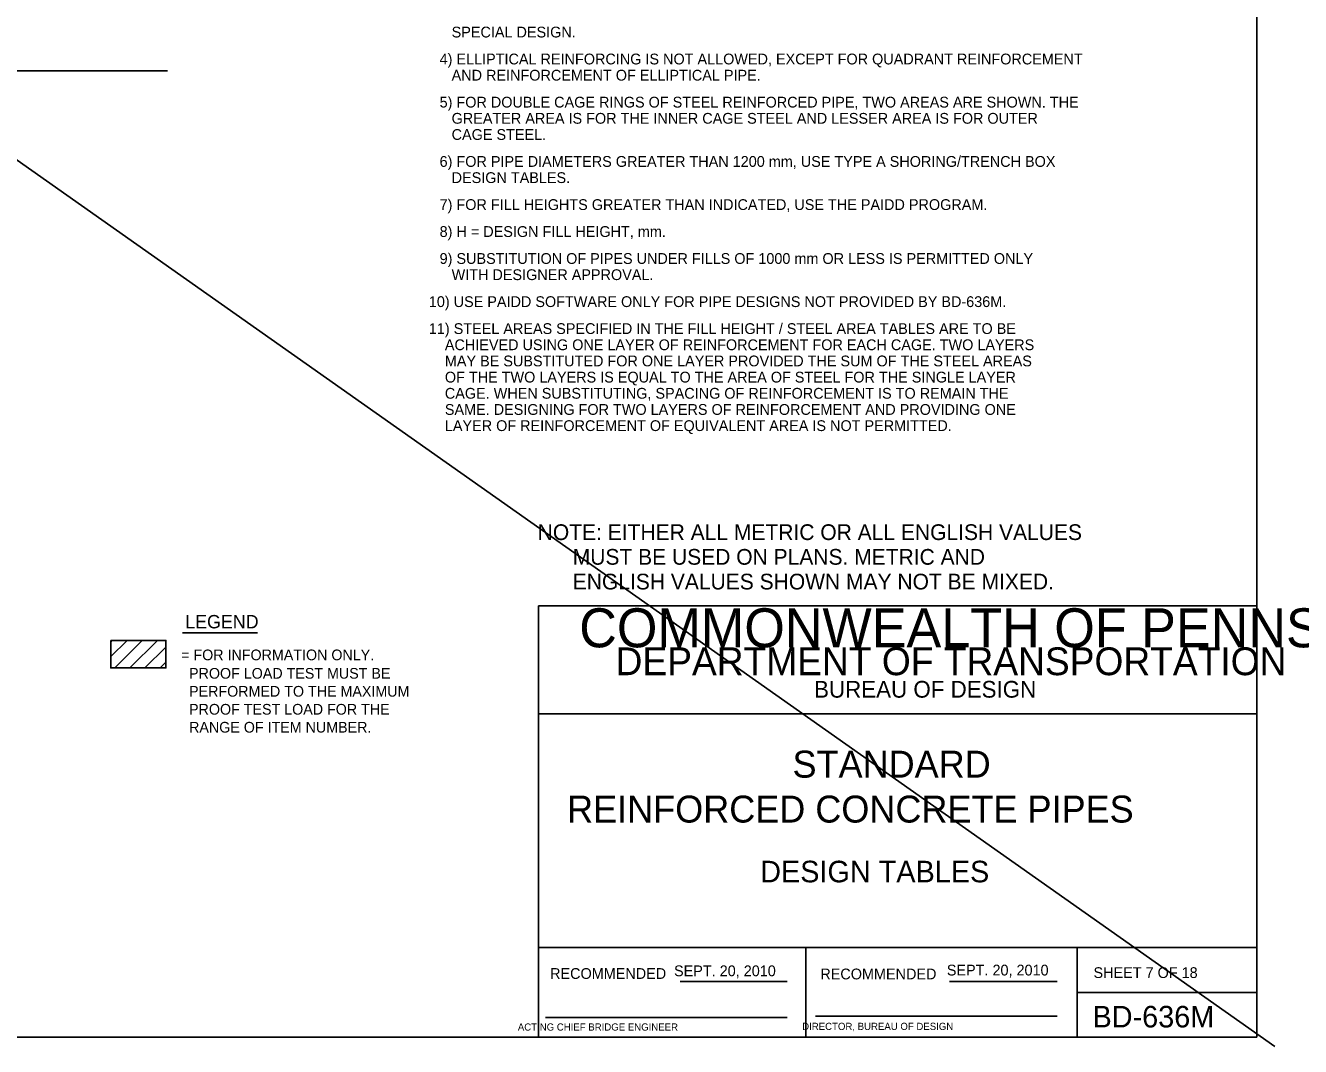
# Model space of a CAD drawing. Extents: x -22562 to -18409, y 3991 to 7171.
# Drawn here: x -20742.6 to -20387.7, y 5785.8 to 6069.9 of the extents above; entities that cross this region are included whole.
import ezdxf

# ---------------------------------------------------------------- set-up
doc = ezdxf.new("R2010")
doc.units = 0
doc.layers.add('2', color=7, linetype='Continuous')
doc.layers.add('Default', color=7, linetype='Continuous')

msp = doc.modelspace()

# ---------------------------------------------------------------- linework, layer by layer
at = {"layer": '2'}
for p, q in [((-20399.85, 6352.37), (-20399.85, 5788.37)), ((-20939.35, 6057.37), (-20703.1, 6057.24)), ((-20399.85, 5908.37), (-20599.85, 5908.37)), ((-20599.85, 5908.37), (-20599.85, 5788.37)), ((-20399.85, 5788.37), (-20399.85, 5908.37)), ((-20718.89, 5898.4), (-20718.52, 5898.78)), ((-20718.89, 5894.28), (-20714.27, 5898.78)), ((-20717.77, 5891.15), (-20710.14, 5898.78)), ((-20713.52, 5891.15), (-20705.89, 5898.78)), ((-20698.89, 5900.9), (-20678.02, 5900.9)), ((-20709.39, 5891.15), (-20703.52, 5896.9)), ((-20705.14, 5891.15), (-20703.52, 5892.78)), ((-20399.85, 5878.37), (-20599.85, 5878.37)), ((-20399.85, 5813.37), (-20599.85, 5813.37)), ((-20525.35, 5788.37), (-20525.35, 5813.37)), ((-20449.85, 5813.37), (-20449.85, 5788.37)), ((-20560.38, 5803.87), (-20530.62, 5803.87)), ((-20485.38, 5803.87), (-20455.47, 5803.87)), ((-20449.85, 5800.87), (-20399.85, 5800.87)), ((-20597.85, 5793.87), (-20530.62, 5793.87)), ((-20522.72, 5794.24), (-20455.47, 5794.24)), ((-20399.85, 5788.37), (-21185.85, 5788.37)), ((-20599.85, 5788.37), (-20399.85, 5788.37))]:
    msp.add_line(p, q, dxfattribs=at)
msp.add_lwpolyline([(-20718.89, 5898.78), (-20703.52, 5898.78), (-20703.52, 5891.15), (-20718.89, 5891.15), (-20718.89, 5898.78)], dxfattribs=at)
at = {"layer": 'Default'}
msp.add_line((-21206.34, 6357.45), (-20394.86, 5785.82), dxfattribs=at)

# ---------------------------------------------------------------- texts
at = {"layer": '2'}
for s, height, p in [('   SPECIAL DESIGN.', 3, (-20627.33, 6066.54)), ('4) ELLIPTICAL REINFORCING IS NOT ALLOWED, EXCEPT FOR QUADRANT REINFORCEMENT', 3, (-20627.33, 6059.04)), ('   AND REINFORCEMENT OF ELLIPTICAL PIPE.', 3, (-20627.33, 6054.54)), ('5) FOR DOUBLE CAGE RINGS OF STEEL REINFORCED PIPE, TWO AREAS ARE SHOWN. THE', 3, (-20627.33, 6047.04)), ('   GREATER AREA IS FOR THE INNER CAGE STEEL AND LESSER AREA IS FOR OUTER', 3, (-20627.33, 6042.54)), ('   CAGE STEEL.', 3, (-20627.33, 6038.04)), ('6) FOR PIPE DIAMETERS GREATER THAN 1200 mm, USE TYPE A SHORING/TRENCH BOX', 3, (-20627.33, 6030.54)), ('   DESIGN TABLES.', 3, (-20627.33, 6026.04)), ('7) FOR FILL HEIGHTS GREATER THAN INDICATED, USE THE PAIDD PROGRAM.', 3, (-20627.33, 6018.54)), ('8) H = DESIGN FILL HEIGHT, mm.', 3, (-20627.33, 6011.04)), ('9) SUBSTITUTION OF PIPES UNDER FILLS OF 1000 mm OR LESS IS PERMITTED ONLY', 3, (-20627.33, 6003.54)), ('   WITH DESIGNER APPROVAL.', 3, (-20627.33, 5999.04)), ('10) USE PAIDD SOFTWARE ONLY FOR PIPE DESIGNS NOT PROVIDED BY BD-636M.', 3, (-20630.33, 5991.54)), ('11) STEEL AREAS SPECIFIED IN THE FILL HEIGHT / STEEL AREA TABLES ARE TO BE', 3, (-20630.33, 5984.04)), ('    ACHIEVED USING ONE LAYER OF REINFORCEMENT FOR EACH CAGE. TWO LAYERS', 3, (-20630.33, 5979.54)), ('    MAY BE SUBSTITUTED FOR ONE LAYER PROVIDED THE SUM OF THE STEEL AREAS', 3, (-20630.33, 5975.04)), ('    OF THE TWO LAYERS IS EQUAL TO THE AREA OF STEEL FOR THE SINGLE LAYER', 3, (-20630.33, 5970.54)), ('    CAGE. WHEN SUBSTITUTING, SPACING OF REINFORCEMENT IS TO REMAIN THE', 3, (-20630.33, 5966.04)), ('    SAME. DESIGNING FOR TWO LAYERS OF REINFORCEMENT AND PROVIDING ONE', 3, (-20630.33, 5961.54)), ('    LAYER OF REINFORCEMENT OF EQUIVALENT AREA IS NOT PERMITTED.', 3, (-20630.33, 5957.04)), ('NOTE: EITHER ALL METRIC OR ALL ENGLISH VALUES', 4.375, (-20600.03, 5926.72)), ('      MUST BE USED ON PLANS. METRIC AND', 4.375, (-20600.03, 5919.85)), ('      ENGLISH VALUES SHOWN MAY NOT BE MIXED.', 4.375, (-20600.03, 5912.97)), ('LEGEND', 3.714, (-20698.14, 5902.15)), ('COMMONWEALTH OF PENNSYLVANIA', 10.8525, (-20588.47, 5896.87)), ('= FOR INFORMATION ONLY.', 2.97, (-20699.27, 5893.28)), ('DEPARTMENT OF TRANSPORTATION', 7.7332, (-20578.35, 5889.12)), ('  PROOF LOAD TEST MUST BE', 2.97, (-20699.27, 5888.15)), ('BUREAU OF DESIGN', 4.6493, (-20523.1, 5882.87)), ('  PERFORMED TO THE MAXIMUM', 2.97, (-20699.27, 5883.15)), ('  PROOF TEST LOAD FOR THE', 2.97, (-20699.27, 5878.15)), ('  RANGE OF ITEM NUMBER.', 2.97, (-20699.27, 5873.15)), ('STANDARD', 7.5, (-20529.1, 5860.62)), ('REINFORCED CONCRETE PIPES', 7.5, (-20591.85, 5848.12)), ('DESIGN TABLES', 6, (-20538.1, 5831.49)), ('SEPT. 20, 2010', 3, (-20562.08, 5805.37)), ('SEPT. 20, 2010', 3, (-20486.15, 5805.57)), ('SHEET 7 OF 18', 3, (-20445.32, 5804.87)), ('BD-636M', 6, (-20445.6, 5791.12)), ('       ACTING CHIEF BRIDGE ENGINEER', 2.0002, (-20610.76, 5790.24))]:
    msp.add_text(s, height=height, dxfattribs=at).set_placement(p)
for s, height, p in [('RECOMMENDED', 3, (-20596.58, 5804.62)), ('RECOMMENDED', 3, (-20521.36, 5804.49)), ('   DIRECTOR, BUREAU OF DESIGN', 2.0002, (-20528.65, 5790.42))]:
    msp.add_text(s, height=height, rotation=360, dxfattribs=at).set_placement(p)

doc.saveas('drawing.dxf')
